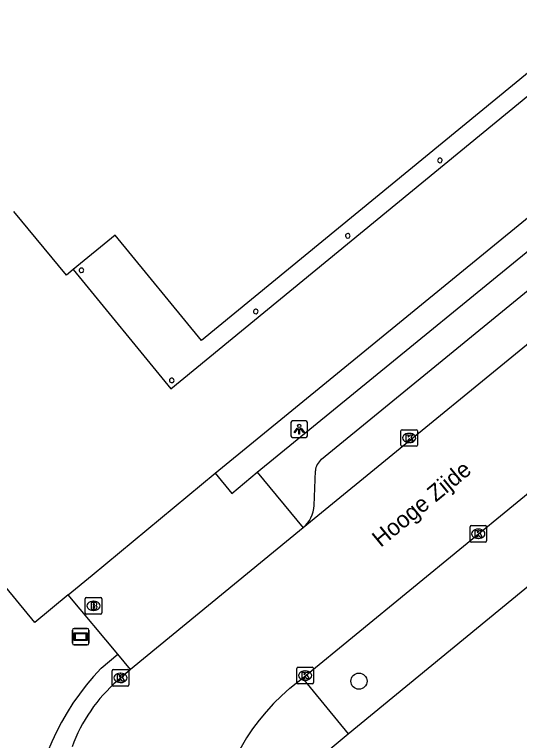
# Model space of a CAD drawing. Extents: x 156651 to 158072, y 387631 to 388990.
# Drawn here: x 156930.1 to 156960.64, y 388166.09 to 388209.98 of the extents above; entities that cross this region are included whole.
import ezdxf

# ---------------------------------------------------------------- set-up
doc = ezdxf.new("R2010")
doc.units = 0
for name, color, linetype in [('IMGEO_Berm_groen', 7, 'Continuous'), ('IMGEO_Boom', 7, 'Continuous'), ('IMGEO_Brandkraan', 7, 'Continuous'), ('IMGEO_Groenvoorziening', 7, 'Continuous'), ('IMGEO_Hek', 7, 'Continuous'), ('IMGEO_Kolk', 7, 'Continuous'), ('IMGEO_Lichtpunt', 7, 'Continuous'), ('IMGEO_Openbare_ruimte_label', 7, 'Continuous'), ('IMGEO_Pand', 7, 'Continuous'), ('IMGEO_Pand_overbouw', 7, 'Continuous'), ('IMGEO_Rijbaan_lokaal_gesloten', 7, 'Continuous'), ('IMGEO_Straatnaambord', 7, 'Continuous'), ('IMGEO_Verkeerseiland_open', 7, 'Continuous'), ('IMGEO_Voetpad_open', 7, 'Continuous')]:
    doc.layers.add(name, color=color, linetype=linetype)

msp = doc.modelspace()

# ---------------------------------------------------------------- linework, layer by layer
at = {"layer": 'IMGEO_Berm_groen'}
for points in [[(156933.339, 388174.89), (156931.323, 388173.236), (156904.219, 388206.202), (156908.067, 388209.288), (156896.52, 388225.881)], [(156950.279, 388166.487), (156967.928, 388180.992)]]:
    msp.add_lwpolyline(points, dxfattribs=at)
at = {"layer": 'IMGEO_Boom'}
msp.add_circle((156950.928, 388169.68), 0.489, dxfattribs=at)
at = {"layer": 'IMGEO_Brandkraan'}
for p, q in [((156934.375, 388173.809), (156934.375, 388174.661)), ((156934.45, 388174.735), (156935.302, 388174.735)), ((156934.863, 388174.515), (156934.888, 388174.515)), ((156935.376, 388174.661), (156935.376, 388173.809)), ((156934.886, 388173.955), (156934.861, 388173.955)), ((156935.302, 388173.735), (156934.45, 388173.735))]:
    msp.add_line(p, q, dxfattribs=at)
for points in [[(156934.375, 388173.809), (156934.375, 388174.661)], [(156934.45, 388174.735), (156935.302, 388174.735)], [(156934.723, 388174.435), (156934.723, 388174.035), (156934.936, 388174.035)], [(156934.954, 388174.435), (156934.723, 388174.435)], [(156935.376, 388174.661), (156935.376, 388173.809)], [(156934.902, 388174.354), (156934.848, 388174.354), (156934.848, 388174.278)], [(156934.848, 388174.278), (156934.901, 388174.278)], [(156934.91, 388174.202), (156934.848, 388174.202), (156934.848, 388174.121)], [(156934.848, 388174.121), (156934.91, 388174.121)], [(156935.302, 388173.735), (156934.45, 388173.735)]]:
    msp.add_lwpolyline(points, dxfattribs=at)
for centre, radius, start, end in [((156934.452, 388174.659), 0.0765, 91.552, 178.448), ((156934.452, 388174.659), 0.0765, 91.552, 178.448), ((156934.958, 388174.29), 0.145, 59.4692, 91.5367), ((156934.983, 388174.337), 0.0922, 285.5137, 58.1501), ((156935.3, 388174.659), 0.0765, 1.552, 88.448), ((156935.3, 388174.659), 0.0765, 1.552, 88.448), ((156934.903, 388174.316), 0.0379, 267.8285, 90.9355), ((156934.911, 388174.161), 0.0404, 269.8759, 90.5077), ((156934.942, 388174.286), 0.251, 268.6676, 293.5347), ((156934.988, 388174.145), 0.105, 301.3115, 78.989), ((156934.452, 388173.811), 0.0765, 181.552, 268.448), ((156934.452, 388173.811), 0.0765, 181.552, 268.448), ((156935.3, 388173.811), 0.0765, 271.552, 358.448), ((156935.3, 388173.811), 0.0765, 271.552, 358.448)]:
    msp.add_arc(centre, radius, start, end, dxfattribs=at)
for centre, major_axis, ratio, start_param, end_param in [((156934.862, 388174.235), (-0.387, 0.002), 0.722429, 4.712389, 7.853982), ((156934.887, 388174.235), (-0.39, 0.002), 0.717154, 1.570796, 4.712389)]:
    msp.add_ellipse(centre, major_axis=major_axis, ratio=ratio, start_param=start_param, end_param=end_param, dxfattribs=at)
at = {"layer": 'IMGEO_Groenvoorziening'}
msp.add_lwpolyline([(156942.229, 388182.248), (156965.861, 388201.554), (156983.313, 388215.956), (156988.363, 388220.001)], dxfattribs=at)
at = {"layer": 'IMGEO_Hek'}
for points in [[(156934.789, 388176.079), (156942.229, 388182.248), (156965.861, 388201.554), (156983.313, 388215.956)], [(156933.339, 388174.89), (156934.789, 388176.079)], [(156933.339, 388174.89), (156931.323, 388173.236)]]:
    msp.add_lwpolyline(points, dxfattribs=at)
at = {"layer": 'IMGEO_Kolk'}
for p, q in [((156953.468, 388183.955), (156953.468, 388184.807)), ((156953.543, 388184.881), (156954.395, 388184.881)), ((156953.956, 388184.661), (156953.981, 388184.661)), ((156954.469, 388184.807), (156954.469, 388183.955)), ((156953.979, 388184.101), (156953.954, 388184.101)), ((156954.395, 388183.881), (156953.543, 388183.881)), ((156957.645, 388178.163), (156957.645, 388179.015)), ((156957.72, 388179.089), (156958.572, 388179.089)), ((156958.133, 388178.869), (156958.158, 388178.869)), ((156958.646, 388179.015), (156958.646, 388178.163)), ((156958.572, 388178.089), (156957.72, 388178.089)), ((156958.156, 388178.309), (156958.131, 388178.309)), ((156947.176, 388169.591), (156947.176, 388170.443)), ((156947.251, 388170.517), (156948.103, 388170.517)), ((156948.177, 388170.443), (156948.177, 388169.591)), ((156936.005, 388169.453), (156936.005, 388170.305)), ((156936.08, 388170.379), (156936.932, 388170.379)), ((156936.493, 388170.159), (156936.518, 388170.159)), ((156937.006, 388170.305), (156937.006, 388169.453)), ((156947.664, 388170.297), (156947.689, 388170.297)), ((156936.516, 388169.599), (156936.491, 388169.599)), ((156947.687, 388169.737), (156947.662, 388169.737)), ((156936.932, 388169.379), (156936.08, 388169.379)), ((156948.103, 388169.517), (156947.251, 388169.517))]:
    msp.add_line(p, q, dxfattribs=at)
for points in [[(156953.468, 388183.955), (156953.468, 388184.807)], [(156953.543, 388184.881), (156954.395, 388184.881)], [(156953.789, 388184.581), (156953.912, 388184.581), (156953.912, 388184.43), (156954.042, 388184.581), (156954.206, 388184.581), (156954.06, 388184.43), (156954.213, 388184.181), (156954.061, 388184.181), (156953.976, 388184.345), (156953.912, 388184.278), (156953.912, 388184.181), (156953.789, 388184.181), (156953.789, 388184.581)], [(156954.469, 388184.807), (156954.469, 388183.955)], [(156954.395, 388183.881), (156953.543, 388183.881)], [(156957.645, 388178.163), (156957.645, 388179.015)], [(156957.72, 388179.089), (156958.572, 388179.089)], [(156957.966, 388178.789), (156958.089, 388178.789), (156958.089, 388178.638), (156958.219, 388178.789), (156958.383, 388178.789), (156958.237, 388178.638), (156958.39, 388178.389), (156958.238, 388178.389), (156958.153, 388178.553), (156958.089, 388178.486), (156958.089, 388178.389), (156957.966, 388178.389), (156957.966, 388178.789)], [(156958.646, 388179.015), (156958.646, 388178.163)], [(156958.572, 388178.089), (156957.72, 388178.089)], [(156947.176, 388169.591), (156947.176, 388170.443)], [(156947.251, 388170.517), (156948.103, 388170.517)], [(156948.177, 388170.443), (156948.177, 388169.591)], [(156936.005, 388169.453), (156936.005, 388170.305)], [(156936.08, 388170.379), (156936.932, 388170.379)], [(156936.326, 388170.079), (156936.449, 388170.079), (156936.449, 388169.928), (156936.579, 388170.079), (156936.743, 388170.079), (156936.597, 388169.928), (156936.75, 388169.679), (156936.598, 388169.679), (156936.513, 388169.843), (156936.449, 388169.776), (156936.449, 388169.679), (156936.326, 388169.679), (156936.326, 388170.079)], [(156937.006, 388170.305), (156937.006, 388169.453)], [(156947.497, 388170.217), (156947.62, 388170.217), (156947.62, 388170.066), (156947.75, 388170.217), (156947.914, 388170.217), (156947.768, 388170.066), (156947.921, 388169.817), (156947.769, 388169.817), (156947.684, 388169.981), (156947.62, 388169.914), (156947.62, 388169.817), (156947.497, 388169.817), (156947.497, 388170.217)], [(156936.932, 388169.379), (156936.08, 388169.379)], [(156948.103, 388169.517), (156947.251, 388169.517)]]:
    msp.add_lwpolyline(points, dxfattribs=at)
for centre, start, end in [((156953.545, 388184.805), 91.552, 178.448), ((156953.545, 388184.805), 91.552, 178.448), ((156954.393, 388184.805), 1.552, 88.448), ((156954.393, 388184.805), 1.552, 88.448), ((156953.545, 388183.957), 181.552, 268.448), ((156953.545, 388183.957), 181.552, 268.448), ((156954.393, 388183.957), 271.552, 358.448), ((156954.393, 388183.957), 271.552, 358.448), ((156957.722, 388179.013), 91.552, 178.448), ((156957.722, 388179.013), 91.552, 178.448), ((156958.57, 388179.013), 1.552, 88.448), ((156958.57, 388179.013), 1.552, 88.448), ((156957.722, 388178.165), 181.552, 268.448), ((156957.722, 388178.165), 181.552, 268.448), ((156958.57, 388178.165), 271.552, 358.448), ((156958.57, 388178.165), 271.552, 358.448), ((156947.253, 388170.441), 91.552, 178.448), ((156947.253, 388170.441), 91.552, 178.448), ((156948.101, 388170.441), 1.552, 88.448), ((156948.101, 388170.441), 1.552, 88.448), ((156936.082, 388170.303), 91.552, 178.448), ((156936.082, 388170.303), 91.552, 178.448), ((156936.93, 388170.303), 1.552, 88.448), ((156936.93, 388170.303), 1.552, 88.448), ((156947.253, 388169.593), 181.552, 268.448), ((156947.253, 388169.593), 181.552, 268.448), ((156948.101, 388169.593), 271.552, 358.448), ((156948.101, 388169.593), 271.552, 358.448), ((156936.082, 388169.455), 181.552, 268.448), ((156936.082, 388169.455), 181.552, 268.448), ((156936.93, 388169.455), 271.552, 358.448), ((156936.93, 388169.455), 271.552, 358.448)]:
    msp.add_arc(centre, 0.0765, start, end, dxfattribs=at)
for centre, major_axis, ratio, start_param, end_param in [((156953.955, 388184.381), (-0.387, 0.002), 0.722429, 4.712389, 7.853982), ((156953.98, 388184.381), (-0.39, 0.002), 0.717154, 1.570796, 4.712389), ((156958.132, 388178.589), (-0.387, 0.002), 0.722429, 4.712389, 7.853982), ((156958.157, 388178.589), (-0.39, 0.002), 0.717154, 1.570796, 4.712389), ((156936.492, 388169.879), (-0.387, 0.002), 0.722429, 4.712389, 7.853982), ((156936.517, 388169.879), (-0.39, 0.002), 0.717154, 1.570796, 4.712389), ((156947.663, 388170.017), (-0.387, 0.002), 0.722429, 4.712389, 7.853982), ((156947.688, 388170.017), (-0.39, 0.002), 0.717154, 1.570796, 4.712389)]:
    msp.add_ellipse(centre, major_axis=major_axis, ratio=ratio, start_param=start_param, end_param=end_param, dxfattribs=at)
at = {"layer": 'IMGEO_Lichtpunt'}
for p, q in [((156947.716, 388185.41), (156946.908, 388185.41)), ((156947.716, 388185.41), (156946.908, 388185.41)), ((156946.814, 388185.315), (156946.814, 388184.508)), ((156946.814, 388185.315), (156946.814, 388184.508)), ((156947.81, 388184.508), (156947.81, 388185.315)), ((156947.81, 388184.508), (156947.81, 388185.315)), ((156946.908, 388184.414), (156947.716, 388184.414)), ((156946.908, 388184.414), (156947.716, 388184.414))]:
    msp.add_line(p, q, dxfattribs=at)
for points in [[(156947.188, 388184.979), (156947.227, 388184.951), (156947.039, 388184.689), (156947.001, 388184.716), (156947.188, 388184.979)], [(156947.29, 388184.931), (156947.337, 388184.931), (156947.337, 388184.609), (156947.29, 388184.609), (156947.29, 388184.931)], [(156947.4, 388184.951), (156947.438, 388184.978), (156947.625, 388184.716), (156947.586, 388184.688), (156947.4, 388184.951)]]:
    msp.add_lwpolyline(points, dxfattribs=at)
msp.add_circle((156947.313, 388185.113), 0.0994, dxfattribs=at)
for centre, start, end in [((156946.908, 388185.315), 90, 180), ((156946.908, 388185.315), 90, 180), ((156947.716, 388185.315), 0, 90), ((156947.716, 388185.315), 0, 90), ((156946.908, 388184.508), 180, 270), ((156946.908, 388184.508), 180, 270), ((156947.716, 388184.508), 270, 0), ((156947.716, 388184.508), 270, 360)]:
    msp.add_arc(centre, 0.0946, start, end, dxfattribs=at)
at = {"layer": 'IMGEO_Pand'}
msp.add_lwpolyline([(156983.663, 388224.94), (156980.491, 388222.335), (156978.06, 388220.344), (156978.012, 388220.304), (156941.415, 388190.276), (156936.176, 388196.64), (156933.645, 388194.564), (156933.233, 388194.214), (156930.06, 388198.078)], dxfattribs=at)
for centre, radius, start, end in [((156955.822, 388201.16), 0.137, 300.758, 234.63), ((156955.822, 388201.161), 0.137, 234.8113, 300.5768), ((156950.252, 388196.602), 0.137, 305.0612, 238.7571), ((156950.252, 388196.601), 0.136, 238.4987, 305.3196), ((156934.144, 388194.519), 0.137, 326.4889, 265.8995), ((156934.143, 388194.521), 0.139, 266.4688, 325.9196), ((156944.686, 388192.028), 0.138, 307.486, 249.8749), ((156944.687, 388192.027), 0.136, 249.6044, 307.7564), ((156939.607, 388187.859), 0.138, 318.16, 251.7516), ((156939.607, 388187.86), 0.139, 252.0415, 317.8702)]:
    msp.add_arc(centre, radius, start, end, dxfattribs=at)
at = {"layer": 'IMGEO_Pand_overbouw'}
msp.add_lwpolyline([(156939.559, 388187.357), (156978.685, 388219.48), (156978.012, 388220.304), (156941.415, 388190.276), (156936.176, 388196.64), (156933.645, 388194.564)], close=True, dxfattribs=at)
at = {"layer": 'IMGEO_Rijbaan_lokaal_gesloten'}
for points in [[(157019.722, 388237.965), (156947.557, 388178.951)], [(156947.504, 388169.869), (156963.742, 388183.161)], [(156947.557, 388178.951), (156937.11, 388170.391)], [(156937.11, 388170.391), (156936.342, 388169.728)], [(156946.742, 388169.256), (156947.504, 388169.869)]]:
    msp.add_lwpolyline(points, dxfattribs=at)
for centre, radius, start, end in [((156942.837, 388162.294), 9.871, 131.1437, 159.8115), ((156955.642, 388158.903), 13.653, 130.6832, 217.97)]:
    msp.add_arc(centre, radius, start, end, dxfattribs=at)
at = {"layer": 'IMGEO_Straatnaambord'}
for p, q in [((156933.6, 388171.972), (156933.6, 388172.772)), ((156933.6, 388172.772), (156933.6, 388171.972)), ((156933.7, 388172.872), (156934.49, 388172.872)), ((156934.49, 388172.872), (156933.7, 388172.872)), ((156934.59, 388172.772), (156934.59, 388171.972)), ((156934.59, 388171.972), (156934.59, 388172.772)), ((156934.49, 388171.872), (156933.7, 388171.872)), ((156933.7, 388171.872), (156934.49, 388171.872))]:
    msp.add_line(p, q, dxfattribs=at)
for points in [[(156933.701, 388172.604), (156934.489, 388172.604), (156934.489, 388172.14), (156933.701, 388172.14), (156933.701, 388172.604)], [(156933.766, 388172.539), (156933.766, 388172.205), (156934.424, 388172.205), (156934.424, 388172.539), (156933.766, 388172.539)]]:
    msp.add_lwpolyline(points, dxfattribs=at)
for centre, start, end in [((156933.7, 388172.772), 90, 180), ((156933.7, 388172.772), 90, 180), ((156934.49, 388172.772), 0, 90), ((156934.49, 388172.772), 360, 90), ((156933.7, 388171.972), 180, 270), ((156933.7, 388171.972), 180, 270), ((156934.49, 388171.972), 270, 0), ((156934.49, 388171.972), 270, 0)]:
    msp.add_arc(centre, 0.1, start, end, dxfattribs=at)
at = {"layer": 'IMGEO_Verkeerseiland_open'}
msp.add_lwpolyline([(156935.341, 388170.471), (156936.34, 388171.309)], dxfattribs=at)
msp.add_arc((156946.293, 388159.895), 15.225, 136.0002, 216.0083, dxfattribs=at)
at = {"layer": 'IMGEO_Voetpad_open'}
for points in [[(156948.653, 388183.095), (157018.331, 388240.059), (157024.565, 388245.043), (157030.887, 388249.913)], [(156944.779, 388182.313), (156989.414, 388218.767), (156988.363, 388220.001)], [(156942.229, 388182.248), (156943.238, 388181.031), (156944.779, 388182.313)], [(156944.779, 388182.313), (156947.557, 388178.951)], [(156948.226, 388180.304), (156948.291, 388182.387)], [(156933.339, 388174.89), (156934.789, 388176.079), (156942.229, 388182.248)], [(156936.34, 388171.309), (156933.339, 388174.89)], [(156937.11, 388170.391), (156936.34, 388171.309)], [(156947.504, 388169.869), (156950.279, 388166.487)], [(156944.652, 388161.796), (156950.279, 388166.487)]]:
    msp.add_lwpolyline(points, dxfattribs=at)
for centre, radius, start, end in [((156949.358, 388182.288), 1.072, 131.143, 174.6957), ((156946.247, 388180.441), 1.984, 311.3313, 356.0479)]:
    msp.add_arc(centre, radius, start, end, dxfattribs=at)

# ---------------------------------------------------------------- texts
at = {"layer": 'IMGEO_Openbare_ruimte_label'}
msp.add_text('Hooge Zijde', height=1, rotation=39.4022, dxfattribs=at).set_placement((156952.24, 388177.733))

doc.saveas('drawing.dxf')
